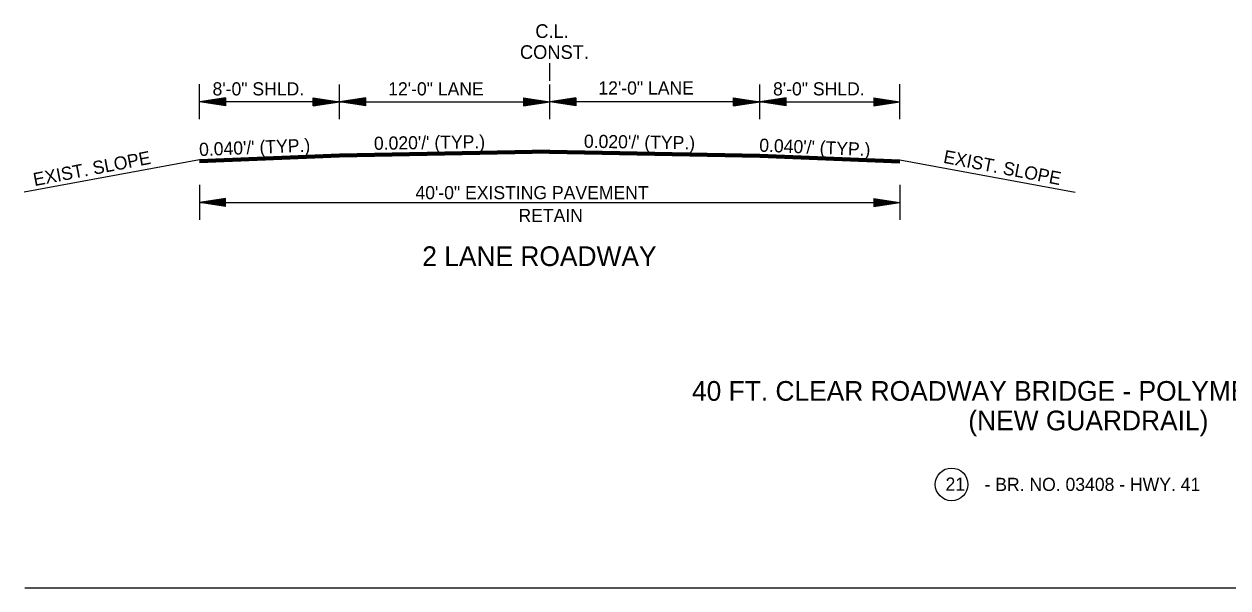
# Model space of a CAD drawing. Extents: x 545241 to 1930787, y -1971772 to 596640.
# Drawn here: x 546719 to 547406, y -1958259 to -1957938 of the extents above; entities that cross this region are included whole.
import ezdxf

# ---------------------------------------------------------------- set-up
doc = ezdxf.new("R2010")
doc.units = 0
doc.layers.add('R_Border', color=7, linetype='Continuous')
doc.layers.add('R_Draft', color=7, linetype='Continuous')

msp = doc.modelspace()

# ---------------------------------------------------------------- linework, layer by layer
at = {"layer": 'R_Border'}
for p, q in [((546898.66, -1958011.96), (546818.66, -1958015.16)), ((546898.66, -1958012.25), (546818.66, -1958015.45)), ((546898.66, -1958012.56), (546818.66, -1958015.76)), ((546898.66, -1958012.86), (546818.66, -1958016.06)), ((546898.66, -1958013.16), (546818.66, -1958016.36)), ((546898.66, -1958013.46), (546818.66, -1958016.66)), ((546898.66, -1958013.63), (546818.66, -1958016.83)), ((547138.66, -1958011.96), (547218.66, -1958015.16)), ((547138.66, -1958012.26), (547218.66, -1958015.46)), ((547138.66, -1958012.56), (547218.66, -1958015.76)), ((547138.66, -1958012.86), (547218.66, -1958016.06)), ((547138.66, -1958013.16), (547218.66, -1958016.36)), ((547138.66, -1958013.46), (547218.66, -1958016.66)), ((547138.66, -1958013.63), (547218.66, -1958016.83)), ((546718.93, -1958259.48), (547746.88, -1958259.48))]:
    msp.add_line(p, q, dxfattribs=at)
msp.add_circle((547248.12, -1958200.38), 9.34, dxfattribs=at)
at = {"layer": 'R_Draft'}
for p, q in [((547018.66, -1957969.93), (547018.66, -1957959.93)), ((546818.66, -1957991.95), (546818.66, -1957971.95)), ((546898.66, -1957991.95), (546898.66, -1957972.06)), ((547018.66, -1957991.95), (547018.66, -1957972.06)), ((547138.66, -1957991.95), (547138.66, -1957972.06)), ((547218.66, -1957991.95), (547218.66, -1957971.95)), ((546833.66, -1957979.7), (546818.66, -1957981.95)), ((546833.66, -1957980.07), (546821.16, -1957981.95)), ((546833.66, -1957980.46), (546823.74, -1957981.95)), ((546833.66, -1957980.83), (546826.24, -1957981.95)), ((546833.66, -1957981.22), (546828.78, -1957981.95)), ((546833.66, -1957981.6), (546831.29, -1957981.95)), ((546833.66, -1957979.7), (546833.66, -1957984.2)), ((546883.66, -1957979.7), (546898.66, -1957981.95)), ((546883.66, -1957984.2), (546883.66, -1957979.7)), ((546883.66, -1957980.07), (546896.15, -1957981.95)), ((546883.66, -1957980.46), (546893.57, -1957981.95)), ((546883.66, -1957980.83), (546891.08, -1957981.95)), ((546883.66, -1957981.21), (546888.53, -1957981.95)), ((546883.66, -1957981.6), (546886.03, -1957981.95)), ((546913.66, -1957979.7), (546898.66, -1957981.95)), ((546913.66, -1957980.07), (546901.16, -1957981.95)), ((546913.66, -1957980.46), (546903.74, -1957981.95)), ((546913.66, -1957980.83), (546906.24, -1957981.95)), ((546913.66, -1957981.21), (546908.78, -1957981.95)), ((546913.66, -1957981.6), (546911.29, -1957981.95)), ((546913.66, -1957984.2), (546913.66, -1957979.7)), ((547003.66, -1957979.7), (547018.66, -1957981.95)), ((547003.66, -1957979.7), (547003.66, -1957984.2)), ((547003.66, -1957980.07), (547016.15, -1957981.95)), ((547003.66, -1957980.46), (547013.57, -1957981.95)), ((547003.66, -1957980.83), (547011.08, -1957981.95)), ((547003.66, -1957981.22), (547008.53, -1957981.95)), ((547003.66, -1957981.6), (547006.03, -1957981.95)), ((547033.66, -1957979.7), (547018.66, -1957981.95)), ((547033.66, -1957980.07), (547021.16, -1957981.95)), ((547033.66, -1957980.46), (547023.74, -1957981.95)), ((547033.66, -1957980.83), (547026.24, -1957981.95)), ((547033.66, -1957981.22), (547028.78, -1957981.95)), ((547033.66, -1957981.6), (547031.29, -1957981.95)), ((547033.66, -1957979.7), (547033.66, -1957984.2)), ((547123.66, -1957979.7), (547138.66, -1957981.95)), ((547123.66, -1957984.2), (547123.66, -1957979.7)), ((547123.66, -1957980.07), (547136.15, -1957981.95)), ((547123.66, -1957980.46), (547133.57, -1957981.95)), ((547123.66, -1957980.83), (547131.08, -1957981.95)), ((547123.66, -1957981.21), (547128.53, -1957981.95)), ((547123.66, -1957981.6), (547126.03, -1957981.95)), ((547153.66, -1957979.7), (547138.66, -1957981.95)), ((547153.66, -1957980.07), (547141.16, -1957981.95)), ((547153.66, -1957980.46), (547143.74, -1957981.95)), ((547153.66, -1957980.83), (547146.24, -1957981.95)), ((547153.66, -1957981.21), (547148.78, -1957981.95)), ((547153.66, -1957981.6), (547151.29, -1957981.95)), ((547153.66, -1957984.2), (547153.66, -1957979.7)), ((547203.66, -1957979.7), (547218.66, -1957981.95)), ((547203.66, -1957979.7), (547203.66, -1957984.2)), ((547203.66, -1957980.07), (547216.15, -1957981.95)), ((547203.66, -1957980.46), (547213.57, -1957981.95)), ((547203.66, -1957980.83), (547211.08, -1957981.95)), ((547203.66, -1957981.22), (547208.53, -1957981.95)), ((547203.66, -1957981.6), (547206.03, -1957981.95)), ((546898.66, -1957981.95), (546818.66, -1957981.95)), ((546833.66, -1957984.2), (546818.66, -1957981.95)), ((546833.66, -1957983.82), (546821.16, -1957981.95)), ((546833.66, -1957983.44), (546823.74, -1957981.95)), ((546833.66, -1957983.07), (546826.24, -1957981.95)), ((546833.66, -1957982.68), (546828.78, -1957981.95)), ((546833.66, -1957982.3), (546831.29, -1957981.95)), ((546883.66, -1957984.2), (546898.66, -1957981.95)), ((546883.66, -1957982.68), (546888.53, -1957981.95)), ((546883.66, -1957983.44), (546893.57, -1957981.95)), ((546883.66, -1957983.82), (546896.15, -1957981.95)), ((546883.66, -1957983.07), (546891.08, -1957981.95)), ((546883.66, -1957982.3), (546886.03, -1957981.95)), ((546913.66, -1957984.2), (546898.66, -1957981.95)), ((546898.66, -1957981.95), (547018.66, -1957981.95)), ((546913.66, -1957983.82), (546901.16, -1957981.95)), ((546913.66, -1957983.44), (546903.74, -1957981.95)), ((546913.66, -1957983.07), (546906.24, -1957981.95)), ((546913.66, -1957982.68), (546908.78, -1957981.95)), ((546913.66, -1957982.3), (546911.29, -1957981.95)), ((547003.66, -1957984.2), (547018.66, -1957981.95)), ((547003.66, -1957982.68), (547008.53, -1957981.95)), ((547003.66, -1957983.44), (547013.57, -1957981.95)), ((547003.66, -1957983.82), (547016.15, -1957981.95)), ((547003.66, -1957983.07), (547011.08, -1957981.95)), ((547003.66, -1957982.3), (547006.03, -1957981.95)), ((547138.66, -1957981.95), (547018.66, -1957981.95)), ((547033.66, -1957984.2), (547018.66, -1957981.95)), ((547033.66, -1957983.82), (547021.16, -1957981.95)), ((547033.66, -1957983.44), (547023.74, -1957981.95)), ((547033.66, -1957983.07), (547026.24, -1957981.95)), ((547033.66, -1957982.68), (547028.78, -1957981.95)), ((547033.66, -1957982.3), (547031.29, -1957981.95)), ((547123.66, -1957984.2), (547138.66, -1957981.95)), ((547123.66, -1957982.68), (547128.53, -1957981.95)), ((547123.66, -1957983.44), (547133.57, -1957981.95)), ((547123.66, -1957983.82), (547136.15, -1957981.95)), ((547123.66, -1957983.07), (547131.08, -1957981.95)), ((547123.66, -1957982.3), (547126.03, -1957981.95)), ((547138.66, -1957981.95), (547218.66, -1957981.95)), ((547153.66, -1957984.2), (547138.66, -1957981.95)), ((547153.66, -1957983.82), (547141.16, -1957981.95)), ((547153.66, -1957983.44), (547143.74, -1957981.95)), ((547153.66, -1957983.07), (547146.24, -1957981.95)), ((547153.66, -1957982.68), (547148.78, -1957981.95)), ((547153.66, -1957982.3), (547151.29, -1957981.95)), ((547203.66, -1957984.2), (547218.66, -1957981.95)), ((547203.66, -1957982.68), (547208.53, -1957981.95)), ((547203.66, -1957983.44), (547213.57, -1957981.95)), ((547203.66, -1957983.82), (547216.15, -1957981.95)), ((547203.66, -1957983.07), (547211.08, -1957981.95)), ((547203.66, -1957982.3), (547206.03, -1957981.95)), ((546818.66, -1958015.16), (546718.59, -1958033.53)), ((547018.66, -1958009.56), (546898.66, -1958011.96)), ((547018.65, -1958009.86), (546898.66, -1958012.26)), ((547018.66, -1958010.16), (546898.66, -1958012.56)), ((547018.68, -1958010.46), (546898.66, -1958012.86)), ((547018.68, -1958010.76), (546898.66, -1958013.16)), ((547018.69, -1958011.06), (546898.66, -1958013.46)), ((547018.69, -1958011.23), (546898.66, -1958013.63)), ((547018.62, -1958011.23), (547138.66, -1958013.63)), ((547018.63, -1958010.76), (547138.66, -1958013.16)), ((547018.63, -1958011.06), (547138.66, -1958013.46)), ((547018.64, -1958010.46), (547138.66, -1958012.86)), ((547018.65, -1958009.86), (547138.66, -1958012.26)), ((547018.65, -1958010.16), (547138.66, -1958012.56)), ((547018.66, -1958009.56), (547138.66, -1958011.96)), ((547218.66, -1958015.16), (547318.73, -1958033.53)), ((546818.66, -1958029.41), (546818.66, -1958049.41)), ((547218.66, -1958029.41), (547218.66, -1958049.41)), ((546833.66, -1958037.16), (546818.66, -1958039.41)), ((546818.66, -1958039.41), (547218.66, -1958039.41)), ((546833.66, -1958041.66), (546818.66, -1958039.41)), ((546833.66, -1958037.54), (546821.16, -1958039.41)), ((546833.66, -1958041.29), (546821.16, -1958039.41)), ((546833.66, -1958037.92), (546823.74, -1958039.41)), ((546833.66, -1958040.91), (546823.74, -1958039.41)), ((546833.66, -1958038.3), (546826.24, -1958039.41)), ((546833.66, -1958040.53), (546826.24, -1958039.41)), ((546833.66, -1958038.68), (546828.78, -1958039.41)), ((546833.66, -1958040.14), (546828.78, -1958039.41)), ((546833.66, -1958039.06), (546831.29, -1958039.41)), ((546833.66, -1958039.77), (546831.29, -1958039.41)), ((546833.66, -1958041.66), (546833.66, -1958037.16)), ((547203.66, -1958037.16), (547218.66, -1958039.41)), ((547203.66, -1958037.16), (547203.66, -1958041.66)), ((547203.66, -1958037.54), (547216.15, -1958039.41)), ((547203.66, -1958037.92), (547213.57, -1958039.41)), ((547203.66, -1958038.3), (547211.08, -1958039.41)), ((547203.66, -1958038.69), (547208.53, -1958039.41)), ((547203.66, -1958039.06), (547206.03, -1958039.41)), ((547203.66, -1958041.66), (547218.66, -1958039.41)), ((547203.66, -1958040.15), (547208.53, -1958039.41)), ((547203.66, -1958040.91), (547213.57, -1958039.41)), ((547203.66, -1958041.29), (547216.15, -1958039.41)), ((547203.66, -1958040.53), (547211.08, -1958039.41)), ((547203.66, -1958039.77), (547206.03, -1958039.41))]:
    msp.add_line(p, q, dxfattribs=at)

# ---------------------------------------------------------------- texts
for s, height, p in [('C.L.', 7.8, (547010.46, -1957945.53)), ('CONST.', 7.8, (547001.68, -1957957.49)), ('8\'-0" SHLD.', 7.5, (546826.18, -1957978.34)), ('12\'-0" LANE', 7.5, (546926.47, -1957978.34)), ('12\'-0" LANE', 7.5, (547046.47, -1957977.82)), ('8\'-0" SHLD.', 7.5, (547146.18, -1957978.34)), ('40\'-0" EXISTING PAVEMENT', 7.5, (546942.03, -1958037.58)), ('RETAIN', 7.5, (547000.85, -1958050.59)), ('2 LANE ROADWAY', 11.25, (546945.93, -1958075.73)), ('40 FT. CLEAR ROADWAY BRIDGE - POLYMER OVERLAY', 11.25, (547099.9, -1958152.65)), ('(NEW GUARDRAIL)', 11.25, (547257.66, -1958169.52)), ('21', 7.5, (547244.66, -1958203.96)), ('- BR. NO. 03408 - HWY. 41', 7.5, (547266.92, -1958204.13))]:
    msp.add_text(s, height=height, dxfattribs=at).set_placement(p)
for s, rotation, p in [("0.020'/' (TYP.)", 0.87191, (546918.38, -1958009.43)), ("0.020'/' (TYP.)", 359.12809, (547038.16, -1958008.2)), ("0.040'/' (TYP.)", 2.29061, (546818.66, -1958012.97)), ("0.040'/' (TYP.)", 357.70939, (547138.21, -1958010.42)), ('EXIST. SLOPE', 10.88286, (546724.57, -1958030.15)), ('EXIST. SLOPE', 349.11714, (547243.04, -1958016.75))]:
    msp.add_text(s, height=7.5, rotation=rotation, dxfattribs=at).set_placement(p)

doc.saveas('drawing.dxf')
